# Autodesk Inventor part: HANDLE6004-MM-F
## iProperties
Category: PARTsolutions
Created: 2007-09
Part Number: HANDLE6004-MM-F
Catalog Web Link: www.cadenas.de
Description: Handle6004mm - Handle
Document SubType Name: Modeling
Designer: PARTsolutions
Material: 1.0037 St 37-2
NB: HANDLE6004-MM-F
NN: Handle6004mm
NT: Handle
NBSYN: $MODELL.-F
LINA: HANDLE6004-MM-F
MODELL: HANDLE6004-MM
HALTEKRAFT: 2600
HUB: 38
GEWICHT: 0.3
EF: 207203-M
BWZ: 604106-M
BMS: 606104-M
KT: DUMMY
PSOL_IDENT_0: {\\partserver001.servicenet\dplatte\cadenas\23d-libs\destaco\destaco_gmbh\man_spann\schubstangenspan
PSOL_IDENT_1: ner\einschraubversion\6004_mm_parts\handle_6004_mm.prj},161 {VTYP=3D},{NB=HANDLE6004-MM-F},{LINA=HAN
PSOL_IDENT_2: DLE6004-MM-F},{NN=Handle6004mm},{DATE=25.1.2005},{GEOMDATE=25.01.2005},{VERSION=v1},{LINEID=20},{LIN
PSOL_IDENT_3: ESUBID=-1},{WBVAR=}  {NB=HANDLE6004-MM-F},{LINA=HANDLE6004-MM-F},{KT=DUMMY},{MODELL=HANDLE6004-MM},{
PSOL_IDENT_4: HALTEKRAFT=2600},{HUB=38},{GEWICHT=0.3},{EF=207203-M},{BWZ=604106-M},{BMS=606104-M}
Title: HANDLE6004-MM-F
Author: Cadenas PARTsolutions
Comments: Handle
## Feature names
1. Extrusion1
2. Extrusion2
3. Extrusion3
4. Extrusion4
5. Extrusion5
6. Revolution1
7. Revolution2
